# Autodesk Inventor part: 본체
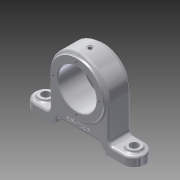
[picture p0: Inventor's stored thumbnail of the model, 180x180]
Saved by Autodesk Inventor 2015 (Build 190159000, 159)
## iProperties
Created: 2019-05
Part Number: 본체
Material: 알루미늄 6061
Document SubType Name: Modeling
Designer: now
Density: 2.7 g/cm^3
Appearance: 알루미늄 - 평지
Mass: 454.985 g
Surface Area: 318.799 cm^2
Volume: 168.513 cm^3
Author: now
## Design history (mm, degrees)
sketch "스케치1"
  geometry: L1 (-75, 0)-(75, 0); L2 (-60, 15)-(60, 15); L3 (60, -15)-(-60, -15); A1 r 15 centre (-60, 0) between (-60, 15) and (-60, -15); A2 r 15 centre (60, 0) between (60, -15) and (60, 15); 2 further points
  constraints: 8 end point, 6 point on circle, 4 tangent, 2 centre point, 2 point on line, 1 coincident, 1 horizontal, 1 midpoint, 1 parallel
  dimensions: "d0" = 120 distance of A2.centre A1.centre; "d2" = 15 radius of A2
extrude "돌출1" new body sketch "스케치1" distance "d3" = 12; taper "d4" = 0 deg
sketch "스케치2"
  geometry: L1 (75, 12)-(75, 0) reference; L2 (75, 0)-(-75, 0) reference; L3 (-75, 0)-(-75, 12) reference; L4 (-75, 12)-(75, 12) reference; C1 r 40 at (0, 60); 2 further points
  constraints: 1 centre point, 1 midpoint, 1 vertical alignment
  dimensions: "d5" = 80 diameter of C1; "d6" = 60 distance of point (0, 0) C1.centre
extrude "돌출2" join sketch "스케치2" stored distance "d7" = 30; taper "d8" = 0 deg
sketch "스케치3"
  geometry: C1 r 40 at (0, 0) reference; C2 r 36 at (0, 0); 1 further point
  constraints: 1 centre point, 1 coincident
  dimensions: "d9" = 72 diameter of C2
extrude "돌출3" join sketch "스케치3" distance "d10" = 3; taper "d11" = 0 deg
sketch "스케치4"
  geometry: C1 r 40 at (0, 0) reference; C2 r 36 at (0, 0); 1 further point
  constraints: 1 centre point, 1 coincident
  dimensions: "d12" = 72 diameter of C2
extrude "돌출4" join sketch "스케치4" distance "d13" = 3; taper "d14" = 0 deg
node "작업 평면1"
sketch "스케치5"
  geometry: L1 (36, -15)-(36, -18) reference; L2 (36, -18)-(-36, -18) reference; L3 (-36, -18)-(-36, -15) reference; L4 (-36, -15)-(-40, -15) reference; L5 (-40, -15)-(-40, 15) reference; L6 (-40, 15)-(-36, 15) reference; L7 (-36, 15)-(-36, 18) reference; L8 (-36, 18)-(36, 18) reference; L9 (36, 18)-(36, 15) reference; L10 (36, 15)-(40, 15) reference; L11 (40, 15)-(40, -15) reference; L12 (40, -15)-(36, -15) reference; L13 (-40, 15)-(40, 15); L14 (40, 15)-(40, -15); L15 (40, -15)-(-40, -15); L16 (-40, -15)-(-40, 15); L17 (-40, 15)-(40, -15); L18 (40, 15)-(-40, -15); 1 further point
  constraints: 12 end point, 2 midpoint, 2 parallel, 1 horizontal, 1 perpendicular
  dimensions: "d16" = 80 distance of L13.start L13.end; "d17" = 30 distance between parallel lines of L13 L15
extrude "돌출5" join sketch "스케치5" stored distance "d18" = 3; taper "d19" = 0 deg
sketch "스케치6"
  geometry: C1 r 9 at (60, 0); A1 r 15 centre (60, 0) between (60, -15) and (60, 15) reference; 1 further point
  constraints: 1 centre point, 1 coincident
  dimensions: "d20" = 18 diameter of C1
extrude "돌출6" join sketch "스케치6" distance "d21" = 3; taper "d22" = 0 deg
hole "구멍1" diameter "d25" = 11; stored, may be unused: countersink angle "d29" = 90 deg, drill point angle "d31" = 118 deg; dims "d23" = 10, "d24" = 10, "d26" = 6, "d27" = 4, "d28" = 2, "d30" = 8
sketch "스케치7"
  geometry: L1 (69, 15)-(69, 12) reference; L2 (69, 12)-(75, 12) reference; L3 (75, 12)-(75, 0) reference; L4 (75, 0)-(65.5, 0) reference; L5 (65.5, 0)-(65.5, 15) reference; L6 (65.5, 15)-(69, 15) reference; L7 (-40, 12)-(-40, 60) reference; L8 (40, 60)-(40, 12) reference; L9 (40, 12)-(51, 12) reference; L10 (51, 12)-(51, 15) reference; L11 (51, 15)-(54.5, 15) reference; L12 (54.5, 15)-(54.5, 0) reference; L13 (54.5, 0)-(-54.5, 0) reference; L14 (-54.5, 0)-(-54.5, 15) reference; L15 (-54.5, 15)-(-51, 15) reference; L16 (-51, 15)-(-51, 12) reference; L17 (-51, 12)-(-40, 12) reference; L18 (-75, 0)-(-75, 12) reference; L19 (-75, 12)-(-69, 12) reference; L20 (-69, 12)-(-69, 15) reference; L21 (-69, 15)-(-65.5, 15) reference; L22 (-65.5, 15)-(-65.5, 0) reference; L23 (-65.5, 0)-(-75, 0) reference; L24 (36, 0)-(-36, 0); L25 (-36, 0)-(-36, 4); L26 (-36, 4)-(36, 4); L27 (36, 4)-(36, 0); L28 (36, 0)-(-36, 4); L29 (-36, 0)-(36, 4); A1 r 40 centre (0, 60) between (40, 60) and (-40, 60) reference; 3 further points
  constraints: 12 end point, 4 midpoint, 2 parallel, 1 horizontal, 1 perpendicular
  dimensions: "d32" = 4 distance between parallel lines of L26 L13; "d33" = 72 distance between parallel lines of L25 L27
extrude "돌출7" cut sketch "스케치7" stored distance "d34" = 3; taper "d35" = 0 deg
sketch "스케치8"
  geometry: L1 (-90, -10)-(-30, -10); L2 (-30, -10)-(-30, 10); L3 (-30, 10)-(-90, 10); L4 (-90, 10)-(-90, -10); L5 (-90, -10)-(-30, 10); L6 (-30, -10)-(-90, 10); 1 further point
  constraints: 12 end point, 2 midpoint, 2 parallel, 1 horizontal, 1 perpendicular
  dimensions: "d36" = 10 distance from line of L3 point (-60, 0); "d37" = 60 distance of L1.start L1.end
extrude "돌출8" cut sketch "스케치8" stored distance "d38" = 0; taper "d39" = 0 deg
node "작업 평면2"
sketch "스케치9"
  geometry: C1 r 3.5 at (0, 0); 1 further point
  constraints: 1 centre point, 1 coincident
  dimensions: "d41" = 7 diameter of C1
extrude "돌출9" cut sketch "스케치9" distance "d42" = 1; taper "d43" = 0 deg
sketch "스케치10"
  geometry: L1 (8.888, -15)-(-8.888, -15) reference; L2 (-8.888, -15)-(-8.888, 15) reference; L3 (-8.888, 15)-(8.888, 15) reference; L4 (8.888, 15)-(8.888, -15) reference; C1 r 3.5 at (0, 0) reference; C2 r 3.5 at (0, 0) reference
hole "구멍2" sketch "스케치10" at (0, 0) diameter "d44" = 4.917; stored, may be unused: countersink angle "d48" = 90 deg, drill point angle "d50" = 118 deg; dims "d45" = 8, "d46" = 6, "d47" = 2, "d49" = 10
sketch "스케치11"
  geometry: C1 r 36 at (0, 0) reference; C2 r 26 at (0, 0); 1 further point
  constraints: 1 centre point, 1 coincident
  dimensions: "d51" = 52 diameter of C2
extrude "돌출10" cut sketch "스케치11" stored distance "d52" = 1; taper "d53" = 0 deg
sketch "스케치12"
  geometry: C1 r 26 at (0, 0) reference; 2 further points
  constraints: 1 vertical alignment
  dimensions: "d54" = 31 distance of point (0, 31) C1.centre
hole "구멍3" sketch "스케치12" at (0, 31) diameter "d55" = 3.242; stored, may be unused: countersink angle "d59" = 90 deg, drill point angle "d61" = 118 deg; dims "d56" = 6, "d57" = 6, "d58" = 2, "d60" = 8
sketch "스케치13"
  geometry: C1 r 1.5 at (0, 26); 2 further points
  constraints: 2 vertical alignment, 1 centre point, 1 other
  dimensions: "d65" = 3 diameter of C1
extrude "돌출11" cut sketch "스케치13" stored distance "d66" = 1; taper "d67" = 0 deg
fillet "모깎기1" dims "d68" = 6
sketch "스케치14"
  geometry: 1 further point
hole "구멍4" sketch "스케치14" at (0, 0) diameter "d69" = 2; stored, may be unused: countersink angle "d73" = 90 deg, drill point angle "d75" = 118 deg; dims "d70" = 6, "d71" = 6, "d72" = 2, "d74" = 30
chamfer "모따기1" distance "d76" = 1; stored, may be unused: second distance "d77" = 2, angle "d78" = 45 deg
fillet "모깎기4" dims "d81" = 3
fillet "모깎기5" dims "d82" = 3
fillet "모깎기6" dims "d83" = 3
fillet "모깎기7" dims "d84" = 3
sketch "스케치15"
  geometry: L1 (33, 10)-(87, 10) reference; 2 further points
  constraints: 1 vertical alignment, 1 other
  dimensions: "d85" = 7 distance from line of L1 point (60, 17)
feature "엠보싱1" sketch "스케치15" dims "d0" = 120, "d2" = 15, "d86" = 0.5, "d87" = 0
node "솔리드1"
mirror "대칭1"
pattern_circular "원형 패턴1" dims angle "d63" = 360 deg
mirror "대칭2"
node "절단 모서리 투영1"
node "절단 모서리 투영2"
node "절단 모서리 투영3"
node "절단 모서리 투영4"
